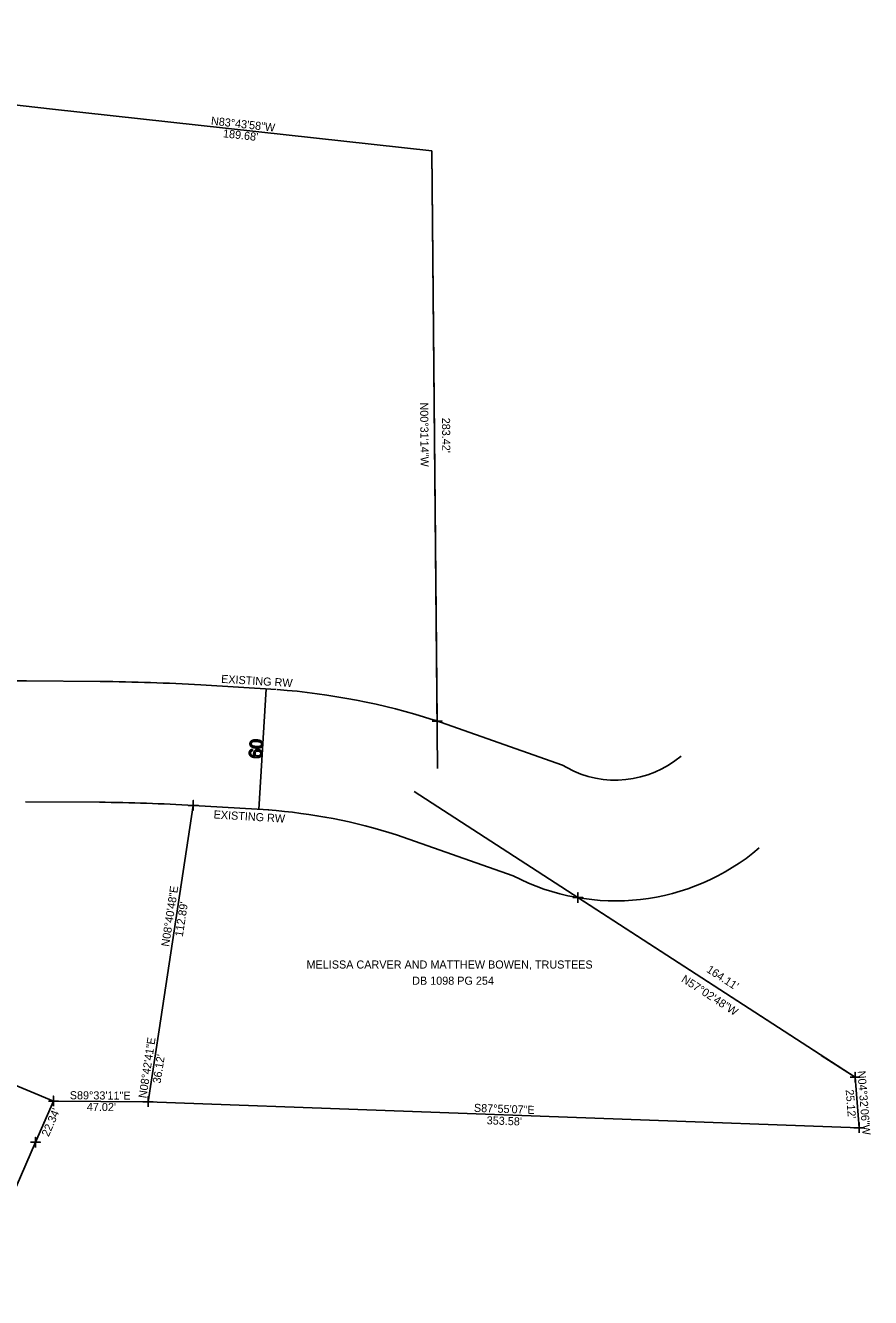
# Model space of a CAD drawing. Extents: x 783966 to 785075, y 667781 to 668938.
# Drawn here: x 784655 to 785075, y 668305 to 668938 of the extents above; entities that cross this region are included whole.
import ezdxf

# ---------------------------------------------------------------- set-up
doc = ezdxf.new("R2010")
doc.units = 0
for name, color, linetype in [('Default', 7, 'Continuous'), ('Exist Property Corner CELL', 7, 'Continuous'), ('Exist Property Line', 7, 'Continuous'), ('Exist Property Text', 7, 'Continuous'), ('Exist Right of Way Line', 7, 'Continuous'), ('Exist Right of Way Text', 7, 'Continuous'), ('Exist Right of Way Width CELL', 7, 'Continuous')]:
    doc.layers.add(name, color=color, linetype=linetype)

msp = doc.modelspace()

# ---------------------------------------------------------------- linework, layer by layer
at = {"layer": 'Default'}
msp.add_line((785067.54, 668414.81), (785050.76, 668425.68), dxfattribs=at)
at = {"layer": 'Exist Property Corner CELL'}
for p, q in [((784859.86, 668591.83), (784859.86, 668591.83)), ((784738.69, 668549.91), (784738.69, 668549.91)), ((784929.83, 668504.08), (784929.83, 668504.08)), ((785067.54, 668414.81), (785067.54, 668414.81)), ((784669.16, 668402.97), (784669.16, 668402.97)), ((784716.18, 668402.61), (784716.18, 668402.61)), ((785069.52, 668389.76), (785069.52, 668389.76)), ((784660.25, 668382.49), (784660.25, 668382.49))]:
    msp.add_line(p, q, dxfattribs=at)
for points in [[(784857.36, 668591.83), (784862.36, 668591.83), (784859.86, 668591.83), (784859.86, 668594.33), (784859.86, 668589.33)], [(784736.19, 668549.91), (784741.19, 668549.91), (784738.69, 668549.91), (784738.69, 668552.41), (784738.69, 668547.41)], [(784927.33, 668504.08), (784932.33, 668504.08), (784929.83, 668504.08), (784929.83, 668506.58), (784929.83, 668501.58)], [(785065.04, 668414.81), (785070.04, 668414.81), (785067.54, 668414.81), (785067.54, 668417.31), (785067.54, 668412.31)], [(784666.66, 668402.97), (784671.66, 668402.97), (784669.16, 668402.97), (784669.16, 668405.47), (784669.16, 668400.47)], [(784713.68, 668402.61), (784718.68, 668402.61), (784716.18, 668402.61), (784716.18, 668405.11), (784716.18, 668400.11)], [(785067.02, 668389.76), (785072.02, 668389.76), (785069.52, 668389.76), (785069.52, 668392.26), (785069.52, 668387.26)], [(784657.75, 668382.49), (784662.75, 668382.49), (784660.25, 668382.49), (784660.25, 668384.99), (784660.25, 668379.99)]]:
    msp.add_lwpolyline(points, dxfattribs=at)
at = {"layer": 'Exist Property Line'}
for p, q in [((784668.73, 668895.94), (784289.56, 668937.51)), ((784857.28, 668875.23), (784668.73, 668895.94)), ((784860.07, 668568.25), (784857.28, 668875.23)), ((784859.86, 668591.83), (784857.28, 668875.23)), ((785067.54, 668414.81), (784848.5, 668556.8)), ((784721.65, 668438.31), (784738.69, 668549.91)), ((785067.54, 668414.81), (784929.83, 668504.08)), ((784536.91, 668458.34), (784669.16, 668402.97)), ((784716.18, 668402.61), (784721.65, 668438.31)), ((785069.52, 668389.76), (785067.54, 668414.81)), ((784660.25, 668382.49), (784669.16, 668402.97)), ((784669.16, 668402.97), (784716.18, 668402.61)), ((784716.18, 668402.61), (785069.52, 668389.76)), ((784626.72, 668305.35), (784660.25, 668382.49))]:
    msp.add_line(p, q, dxfattribs=at)
at = {"layer": 'Exist Right of Way Line'}
for p, q in [((784655.73, 668611.76), (784692.48, 668611.48)), ((784742.46, 668609.79), (784779.9, 668607.53)), ((784858.33, 668592.35), (784858.77, 668592.21)), ((784858.77, 668592.21), (784922.09, 668569.91)), ((784922.09, 668569.91), (784924.25, 668568.72)), ((784655.27, 668551.76), (784692.03, 668551.49)), ((784655.27, 668551.76), (784692.03, 668551.49)), ((784738.85, 668549.9), (784776.29, 668547.64)), ((784738.85, 668549.9), (784776.29, 668547.64)), ((784839.7, 668535.31), (784897.68, 668514.89))]:
    msp.add_line(p, q, dxfattribs=at)
for centre, radius, start, end in [((784648.69, 667681.79), 930, 89.56667, 97.13333), ((784685.3, 667661.51), 950, 86.55, 89.56667), ((784754.51, 668266.27), 342.21, 72.3384, 85.66659), ((784948.5, 668612.78), 50.3, 241.17537, 310.39026), ((784685.3, 667661.51), 890, 86.55, 89.56667), ((784685.3, 667661.51), 890, 86.55, 89.56667), ((784754.51, 668266.27), 282.21, 72.4287, 85.66659), ((784948.5, 668612.78), 110.3, 242.56039, 310.39026)]:
    msp.add_arc(centre, radius, start, end, dxfattribs=at)
at = {"layer": 'Exist Right of Way Width CELL'}
for p, q in [((784774.93, 668607.83), (784771.32, 668547.94)), ((784769.96, 668579.21), (784769.96, 668579.21)), ((784768.15, 668577.02), (784768.13, 668577.78)), ((784769.91, 668578.42), (784769.91, 668578.42)), ((784770.63, 668574.48), (784770.63, 668574.48))]:
    msp.add_line(p, q, dxfattribs=at)
msp.add_lwpolyline([(784771.32, 668547.94), (784771.33, 668548.2), (784771.44, 668547.97)], dxfattribs=at)
for points in [[(784767.11, 668581.51), (784766.88, 668581.14), (784766.85, 668580.64)], [(784766.85, 668580.64), (784766.81, 668579.96), (784767.15, 668579.49)], [(784767.73, 668582.1), (784767.33, 668581.88), (784767.11, 668581.51)], [(784767.15, 668579.49), (784767.48, 668579.02), (784768.15, 668578.75)], [(784767.48, 668580.6), (784767.51, 668581.13), (784768.04, 668581.46)], [(784767.88, 668579.73), (784767.45, 668580.07), (784767.48, 668580.6)], [(784768.68, 668582.43), (784768.12, 668582.32), (784767.73, 668582.1)], [(784769.96, 668579.21), (784768.42, 668579.3), (784767.88, 668579.73)], [(784768.04, 668581.46), (784768.57, 668581.79), (784770.11, 668581.69)], [(784770.16, 668582.48), (784769.23, 668582.54), (784768.68, 668582.43)], [(784772.03, 668579.44), (784771.5, 668579.11), (784769.96, 668579.21)], [(784770.11, 668581.69), (784771.65, 668581.6), (784772.13, 668581.21)], [(784771.92, 668582.15), (784771.26, 668582.42), (784770.16, 668582.48)], [(784772.92, 668581.41), (784772.58, 668581.89), (784771.92, 668582.15)], [(784772.59, 668580.3), (784772.56, 668579.77), (784772.03, 668579.44)], [(784772.13, 668581.21), (784772.62, 668580.82), (784772.59, 668580.3)], [(784772.49, 668578.88), (784773.16, 668579.36), (784773.22, 668580.26)], [(784773.22, 668580.26), (784773.26, 668580.94), (784772.92, 668581.41)], [(784766.96, 668577.28), (784766.52, 668576.84), (784766.47, 668576.1)], [(784766.47, 668576.1), (784766.41, 668575.11), (784767.09, 668574.49)], [(784768.13, 668577.78), (784767.4, 668577.73), (784766.96, 668577.28)], [(784767.09, 668574.49), (784767.87, 668573.77), (784769.68, 668573.66)], [(784767.1, 668576.02), (784767.13, 668576.47), (784767.47, 668576.76)], [(784767.26, 668575.36), (784767.08, 668575.65), (784767.1, 668576.02)], [(784768, 668574.74), (784767.51, 668574.98), (784767.26, 668575.36)], [(784767.47, 668576.76), (784767.69, 668576.94), (784768.15, 668577.02)], [(784769.43, 668574.44), (784768.49, 668574.5), (784768, 668574.74)], [(784768.15, 668578.75), (784768.81, 668578.48), (784769.91, 668578.42)], [(784769.33, 668577.28), (784768.74, 668576.77), (784768.69, 668576)], [(784768.69, 668576), (784768.66, 668575.57), (784768.84, 668575.15)], [(784768.84, 668575.15), (784769.02, 668574.74), (784769.43, 668574.44)], [(784770.82, 668577.73), (784769.93, 668577.78), (784769.33, 668577.28)], [(784769.68, 668574.9), (784769.33, 668575.29), (784769.36, 668575.81)], [(784769.36, 668575.81), (784769.39, 668576.33), (784769.78, 668576.65)], [(784770.63, 668574.48), (784770.03, 668574.52), (784769.68, 668574.9)], [(784769.68, 668573.66), (784771.3, 668573.56), (784772.04, 668574.12)], [(784769.78, 668576.65), (784770.17, 668576.97), (784770.82, 668576.94)], [(784769.91, 668578.42), (784771.67, 668578.31), (784772.49, 668578.88)], [(784771.4, 668574.61), (784771.03, 668574.46), (784770.63, 668574.48)], [(784771.9, 668577.41), (784771.41, 668577.69), (784770.82, 668577.73)], [(784770.82, 668576.94), (784771.49, 668576.89), (784771.87, 668576.52)], [(784771.98, 668575.04), (784771.77, 668574.75), (784771.4, 668574.61)], [(784771.87, 668576.52), (784772.24, 668576.15), (784772.21, 668575.67)], [(784772.63, 668576.67), (784772.39, 668577.12), (784771.9, 668577.41)], [(784772.21, 668575.67), (784772.19, 668575.33), (784771.98, 668575.04)], [(784772.04, 668574.12), (784772.78, 668574.69), (784772.84, 668575.64)], [(784772.84, 668575.64), (784772.87, 668576.21), (784772.63, 668576.67)]]:
    msp.add_open_spline(points, degree=2, dxfattribs=at)

# ---------------------------------------------------------------- texts
at = {"layer": 'Exist Property Text'}
for s, rotation, p in [('N83°43\'58"W', 353.73276, (784747.32, 668888.2)), ("189.68'", 353.73276, (784753.31, 668881.97)), ('N00°31\'14"W', 270.52059, (784851.4, 668750.14)), ("283.42'", 270.52059, (784862.27, 668742.55)), ('N08°40\'48"E', 81.32006, (784726.66, 668479.52)), ("112.89'", 81.32006, (784733.45, 668484.44)), ('N57°02\'48"W', 327.0467, (784980.88, 668462.62)), ("164.11'", 327.0467, (784993.37, 668467.39)), ('N08°42\'41"E', 81.28855, (784715.35, 668404.2)), ("36.12'", 81.28855, (784722.41, 668411.54)), ('N04°32\'06"W', 274.535, (785068.72, 668417.9)), ('S89°33\'11"E', 359.55305, (784677.29, 668403.9)), ("25.12'", 274.535, (785062.88, 668408.55)), ("22.34'", 66.50333, (784666.79, 668384.99)), ("47.02'", 359.55305, (784685.77, 668398.11)), ('S87°55\'07"E', 357.9186, (784878.09, 668397.65)), ("353.58'", 357.9186, (784884.45, 668391.45))]:
    msp.add_text(s, height=4.02, rotation=rotation, dxfattribs=at).set_placement(p)
for s, p in [('MELISSA CARVER AND MATTHEW BOWEN, TRUSTEES', (784794.97, 668468.84)), ('DB 1098 PG 254', (784847.45, 668460.8))]:
    msp.add_text(s, height=4.02, dxfattribs=at).set_placement(p)
at = {"layer": 'Exist Right of Way Text'}
for p in [(784752.42, 668610.83), (784748.7, 668543.47)]:
    msp.add_text('EXISTING RW', height=4.02, rotation=356.55, dxfattribs=at).set_placement(p)

doc.saveas('drawing.dxf')
